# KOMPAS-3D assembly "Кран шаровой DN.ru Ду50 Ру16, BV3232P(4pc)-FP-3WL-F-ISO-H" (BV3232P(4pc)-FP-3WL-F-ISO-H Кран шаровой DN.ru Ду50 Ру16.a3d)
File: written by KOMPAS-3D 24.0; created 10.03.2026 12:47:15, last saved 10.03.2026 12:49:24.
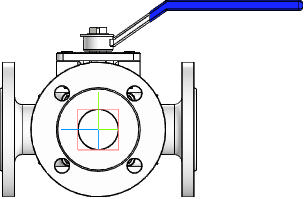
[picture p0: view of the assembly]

Document properties: Автор: R2D2; Полное имя файла: E:\Работа\Зайцев\BV3232P(4pc)-FP-3WL-F-ISO-H Кран шаровой DN.ru Ду15-100 Ру16\DN50\исходные материалы\BV3232P(4pc)-FP-3WL-F-ISO-H Кран шаровой DN.ru Ду50 Ру16.a3d

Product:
- Component [assembly]: Сборка1  | qty 1  | Масса: 19.818804; Автор: R2D2; source file: dn50_3d_step.a3d
- Part/product: Кран шаровой DN.ru Ду50 Ру16  | designation BV3232P(4pc)-FP-3WL-F-ISO-H
    Масса: 17.95
    Раздел спецификации: Прочие изделия
    Примечание: D160-36360

Referenced files in E:\Работа\Зайцев\BV3232P(4pc)-FP-3WL-F-ISO-H Кран шаровой DN.ru Ду15-100 Ру16\DN50\исходные материалы\: dn50_3d_step.a3d
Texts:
  BV3232P(4pc)-FP-3WL-F-ISO-H
  Сборка1 Сборка1
  Ось Z.Начало координат
  Ось Y.Начало координат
